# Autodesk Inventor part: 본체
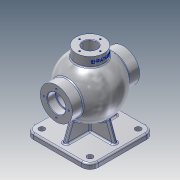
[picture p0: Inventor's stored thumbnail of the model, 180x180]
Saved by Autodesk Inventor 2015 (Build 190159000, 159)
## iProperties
Created: 2025-08
Part Number: 본체
Material: 알루미늄 6061
Document SubType Name: Modeling
Designer: USER
Density: 2.7 g/cm^3
Appearance: 알루미늄 - 평지
Mass: 1526.72 g
Surface Area: 1173.82 cm^2
Volume: 565.453 cm^3
Author: USER
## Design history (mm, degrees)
sketch "스케치1"
  geometry: L1 (-62.5, 62.5)-(62.5, 62.5); L2 (62.5, 62.5)-(62.5, -62.5); L3 (62.5, -62.5)-(-62.5, -62.5); L4 (-62.5, -62.5)-(-62.5, 62.5); L5 (-62.5, 62.5)-(62.5, -62.5); L6 (62.5, 62.5)-(-62.5, -62.5); 1 further point
  constraints: 12 end point, 2 midpoint, 2 parallel, 1 horizontal, 1 perpendicular
  dimensions: "d0" = 125 distance of L1.start L1.end; "d1" = 125 distance of L1.end L2.end
extrude "돌출1" new body sketch "스케치1" distance "d2" = 10; taper "d3" = 0 deg
sketch "스케치2"
  geometry: L1 (-62.5, 0)-(62.5, 0) reference; L2 (0, 31)-(0, 139); A1 r 54 centre (0, 85) between (0, 31) and (0, 139); A2 r 44 centre (0, 85) between (0, 41) and (0, 129); 4 further points
  constraints: 4 point on circle, 3 midpoint, 2 centre point, 2 end point, 2 point on line, 2 vertical alignment, 1 coincident, 1 vertical
  dimensions: "d4" = 85 distance from line of L1 A1.centre; "d5" = 54 radius of A1; "d7" = 44 radius of A2
revolve "회전2" sketch "스케치2" stored, may be unused: angle "d8" = 90 deg
node "작업 평면1"
sketch "스케치3"
  geometry: C1 r 27 at (0, 0); 1 further point
  constraints: 1 centre point, 1 coincident
  dimensions: "d10" = 54 diameter of C1
extrude "돌출2" join sketch "스케치3" stored distance "d11" = 10; taper "d12" = 0 deg
hole "구멍1" diameter "d15" = 26; stored, may be unused: countersink angle "d19" = 90 deg, drill point angle "d21" = 0 deg; dims "d16" = 6, "d17" = 4, "d18" = 2, "d20" = 30, "d22" = 10, "d23" = 10
sketch "스케치4"
  geometry: L1 (0, 0)-(0, 20)
  constraints: 2 end point, 1 vertical
  dimensions: "d24" = 20 distance of L1.start L1.end
hole "구멍2" sketch "스케치4" at (0, 20) diameter "d25" = 3.242; stored, may be unused: countersink angle "d29" = 90 deg, drill point angle "d31" = 118 deg; dims "d26" = 9, "d27" = 4, "d28" = 2, "d30" = 11
node "작업 평면2"
sketch "스케치5"
  geometry: L1 (-62.5, 0)-(62.5, 0) reference; C1 r 31 at (0, 85); 2 further points
  constraints: 1 centre point, 1 midpoint, 1 vertical alignment
  dimensions: "d36" = 62 diameter of C1; "d37" = 85 distance from line of C1.centre L1
extrude "돌출3" join sketch "스케치5" stored distance "d38" = 10; taper "d39" = 0 deg
hole "구멍3" diameter "d42" = 30; stored, may be unused: countersink angle "d46" = 90 deg, drill point angle "d48" = 118 deg; dims "d40" = 10, "d41" = 10, "d43" = 9, "d44" = 35, "d45" = 16, "d47" = 40
sketch "스케치6"
  geometry: L1 (0, 0)-(0, 24); C1 r 31 at (0, 0) reference; 1 further point
  constraints: 2 end point, 1 vertical
  dimensions: "d49" = 24 distance of L1.start L1.end
hole "구멍4" sketch "스케치6" at (0, 24) diameter "d50" = 3.242; stored, may be unused: countersink angle "d54" = 90 deg, drill point angle "d56" = 118 deg; dims "d51" = 12, "d52" = 35, "d53" = 16, "d55" = 15
chamfer "모따기1" distance "d61" = 1; stored, may be unused: second distance "d62" = 2, angle "d63" = 45 deg
fillet "모깎기1" dims "d60" = 0.6
chamfer "모따기2" distance "d64" = 1; stored, may be unused: second distance "d65" = 2, angle "d66" = 45 deg
sketch "스케치7"
  geometry: L1 (-62.5, 62.5)-(62.5, 62.5) reference; L2 (62.5, 62.5)-(62.5, -62.5) reference; L3 (62.5, -62.5)-(-62.5, -62.5) reference; L4 (-62.5, -62.5)-(-62.5, 62.5) reference; L5 (50.5, -4)-(-50.5, -4); L6 (-50.5, -4)-(-50.5, 4); L7 (-50.5, 4)-(50.5, 4); L8 (50.5, 4)-(50.5, -4); L9 (50.5, -4)-(-50.5, 4); L10 (-50.5, -4)-(50.5, 4); L11 (4, 50.5)-(-4, 50.5); L12 (-4, 50.5)-(-4, -50.5); L13 (-4, -50.5)-(4, -50.5); L14 (4, -50.5)-(4, 50.5); L15 (4, 50.5)-(-4, -50.5); L16 (-4, 50.5)-(4, -50.5); 1 further point
  constraints: 24 end point, 4 midpoint, 4 parallel, 2 horizontal, 2 perpendicular
  dimensions: "d67" = 8 distance of L5.end L6.end; "d68" = 8 distance of L11.start L11.end; "d69" = 12 distance between parallel lines of L1 L11; "d70" = 12 distance between parallel lines of L4 L6
extrude "돌출4" join sketch "스케치7" stored distance "d71" = 60; taper "d72" = 0 deg
feature "면 기울기1" dims angle "d73" = 20 deg
fillet "모깎기2" dims "d74" = 16
sketch "스케치8"
  geometry: L1 (4, 50.5)-(4, 4) reference; L2 (4, 4)-(50.5, 4) reference; L3 (50.5, 4)-(50.5, -4) reference; L4 (50.5, -4)-(4, -4) reference; L5 (4, -4)-(4, -50.5) reference; L6 (4, -50.5)-(-4, -50.5) reference; L7 (-4, -50.5)-(-4, -4) reference; L8 (-4, -4)-(-50.5, -4) reference; L9 (-50.5, -4)-(-50.5, 4) reference; L10 (-50.5, 4)-(-4, 4) reference; L11 (-4, 4)-(-4, 50.5) reference; L12 (-4, 50.5)-(4, 50.5) reference; L13 (62.5, -46.5)-(62.5, 46.5) reference; L14 (46.5, 62.5)-(-46.5, 62.5) reference; L15 (-62.5, 46.5)-(-62.5, -46.5) reference; L16 (-46.5, -62.5)-(46.5, -62.5) reference; C1 r 5.5 at (46.5, 46.5); C2 r 5.5 at (46.5, -46.5); C3 r 5.5 at (-46.5, -46.5); C4 r 5.5 at (-46.5, 46.5); A1 r 16 centre (46.5, -46.5) between (46.5, -62.5) and (62.5, -46.5) reference; A2 r 16 centre (46.5, 46.5) between (62.5, 46.5) and (46.5, 62.5) reference; A3 r 16 centre (-46.5, 46.5) between (-46.5, 62.5) and (-62.5, 46.5) reference; A4 r 16 centre (-46.5, -46.5) between (-62.5, -46.5) and (-46.5, -62.5) reference; 1 further point
  constraints: 4 centre point, 4 coincident, 3 equal radius
  dimensions: "d75" = 11 diameter of C1
extrude "돌출5" cut sketch "스케치8" stored distance "d76" = 60; taper "d77" = 0 deg
fillet "모깎기3" dims "d78" = 3
fillet "모깎기4" dims "d79" = 3
fillet "모깎기5" dims "d80" = 3
sketch "스케치9"
  geometry: L1 (27, 150)-(-27, 150) reference; 2 further points
  constraints: 1 vertical alignment, 1 other
  dimensions: "d81" = 9 distance from line of point (0, 141) L1
feature "엠보싱1" sketch "스케치9" dims "d0" = 125, "d1" = 125, "d10" = 54, "d82" = 0.5, "d83" = 0
node "솔리드1"
pattern_circular "원형 패턴1" dims angle "d33" = 360 deg
mirror "대칭1"
pattern_circular "원형 패턴3" dims angle "d85" = 360 deg
mirror "대칭2"
node "투영된 루프1"
node "투영된 루프2"
other parameters: "d35" = -65
